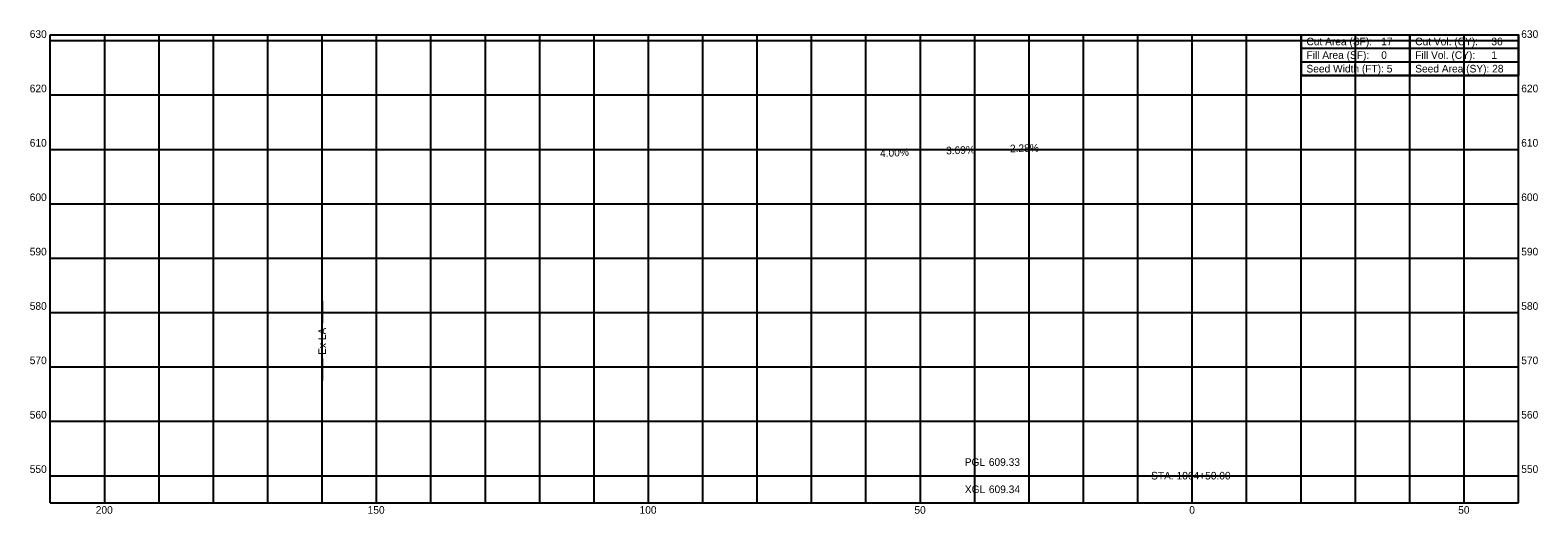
# Model space of a CAD drawing. Extents: x -214 to 64, y 543 to 632.
import ezdxf

# ---------------------------------------------------------------- set-up
doc = ezdxf.new("R2010")
doc.units = 0
for name, color, linetype in [('Default', 7, 'Continuous'), ('DT_X_Void', 7, 'Continuous'), ('SH_Data', 7, 'Continuous'), ('SH_Major_Grid_Line', 7, 'Continuous'), ('SH_Masking', 7, 'Continuous'), ('SH_Text', 7, 'Continuous')]:
    doc.layers.add(name, color=color, linetype=linetype)

msp = doc.modelspace()

# ---------------------------------------------------------------- linework, layer by layer
at = {"layer": 'Default'}
msp.add_circle((60, 631.09), 0.000833, dxfattribs=at)
msp.add_circle((60, 631.09), 0.000833, dxfattribs=at)
msp.add_circle((60, 631.09), 0.000833, dxfattribs=at)
msp.add_circle((60, 631.09), 0.000833, dxfattribs=at)
msp.add_circle((60, 631.09), 0.000833, dxfattribs=at)
msp.add_circle((60, 631.09), 0.000833, dxfattribs=at)
msp.add_circle((60, 631.09), 0.000833, dxfattribs=at)
msp.add_circle((60, 631.09), 0.000833, dxfattribs=at)
msp.add_circle((60, 631.09), 0.000833, dxfattribs=at)
msp.add_circle((60, 631.09), 0.000833, dxfattribs=at)
msp.add_circle((60, 631.09), 0.000833, dxfattribs=at)
msp.add_circle((60, 631.09), 0.000833, dxfattribs=at)
at = {"layer": 'DT_X_Void'}
for p, q in [((-160, 582.14), (-160, 578.07)), ((-160, 571.56), (-160, 567.49))]:
    msp.add_line(p, q, dxfattribs=at)
at = {"layer": 'SH_Data'}
for p, q in [((20, 631.09), (60, 631.09)), ((20, 631.09), (20, 626.09)), ((40, 631.09), (40, 623.59)), ((60, 631.09), (60, 626.09)), ((20, 628.59), (60, 628.59)), ((20, 626.09), (60, 626.09)), ((36.6, 624.84), (36.6, 624.84)), ((55.89, 624.84), (55.89, 624.84))]:
    msp.add_line(p, q, dxfattribs=at)
msp.add_lwpolyline([(20, 626.09), (20, 623.59), (60, 623.59), (60, 626.09)], dxfattribs=at)
at = {"layer": 'SH_Major_Grid_Line'}
for p, q in [((-210, 631.09), (60, 631.09)), ((-210, 545), (-210, 631.09)), ((-210, 630), (60, 630)), ((-200, 545), (-200, 631.09)), ((-190, 545), (-190, 631.09)), ((-180, 545), (-180, 631.09)), ((-170, 545), (-170, 631.09)), ((-160, 545), (-160, 631.09)), ((-150, 545), (-150, 631.09)), ((-140, 545), (-140, 631.09)), ((-130, 545), (-130, 631.09)), ((-120, 545), (-120, 631.09)), ((-110, 545), (-110, 631.09)), ((-100, 545), (-100, 631.09)), ((-90, 545), (-90, 631.09)), ((-80, 545), (-80, 631.09)), ((-70, 545), (-70, 631.09)), ((-60, 545), (-60, 631.09)), ((-50, 545), (-50, 631.09)), ((-40, 545), (-40, 631.09)), ((-30, 545), (-30, 631.09)), ((-20, 545), (-20, 631.09)), ((-10, 545), (-10, 631.09)), ((0, 545), (0, 631.09)), ((10, 545), (10, 631.09)), ((20, 545), (20, 631.09)), ((30, 545), (30, 631.09)), ((40, 545), (40, 631.09)), ((50, 545), (50, 631.09)), ((60, 545), (60, 631.09)), ((-210, 620), (60, 620)), ((-210, 610), (60, 610)), ((-210, 600), (60, 600)), ((-210, 590), (60, 590)), ((-210, 580), (60, 580)), ((-210, 570), (60, 570)), ((-210, 560), (60, 560)), ((-210, 550), (60, 550)), ((-210, 545), (60, 545))]:
    msp.add_line(p, q, dxfattribs=at)
at = {"layer": 'SH_Masking'}
msp.add_lwpolyline([(20, 631.09), (60, 631.09), (60, 623.59), (20, 623.59)], close=True, dxfattribs=at)

# ---------------------------------------------------------------- texts
at = {"layer": 'DT_X_Void'}
msp.add_text('Ex LA', height=1.4, rotation=90, dxfattribs=at).set_placement((-159.3, 572.2))
at = {"layer": 'SH_Text'}
for s, p in [('630', (-213.78, 630.5)), ('Cut Area (SF):', (21, 629.14)), ('17', (34.75, 629.14)), ('Cut Vol. (CY):', (41, 629.14)), ('36', (55, 629.14)), ('630', (60.5, 630.5)), ('Fill Area (SF):', (21, 626.64)), ('0', (34.75, 626.64)), ('Fill Vol. (CY):', (41, 626.64)), ('1', (55, 626.64)), ('Seed Width (FT): 5', (21, 624.14)), ('Seed Area (SY): 28', (41, 624.14)), ('620', (-213.78, 620.5)), ('620', (60.5, 620.5)), ('610', (-213.78, 610.5)), ('610', (60.5, 610.5)), ('600', (-213.78, 600.5)), ('600', (60.5, 600.5)), ('590', (-213.78, 590.5)), ('590', (60.5, 590.5)), ('580', (-213.78, 580.5)), ('580', (60.5, 580.5)), ('570', (-213.78, 570.5)), ('570', (60.5, 570.5)), ('560', (-213.78, 560.5)), ('560', (60.5, 560.5)), ('550', (-213.78, 550.5)), ('PGL ', (-41.84, 551.8)), ('609.33', (-37.41, 551.8)), ('550', (60.5, 550.5)), ('STA. 1064+50.00', (-7.57, 549.3)), ('XGL ', (-41.82, 546.8)), ('609.34', (-37.4, 546.8)), ('200', (-201.64, 543)), ('150', (-151.64, 543)), ('100', (-101.64, 543)), ('50', (-51.1, 543)), ('0', (-0.55, 543)), ('50', (48.9, 543))]:
    msp.add_text(s, height=1.4, dxfattribs=at).set_placement(p)
for s, rotation, p in [('4.00%', 2.291, (-57.39, 608.59)), ('3.69%', 2.115, (-45.25, 609.07)), ('2.28%', 1.3075, (-33.51, 609.46))]:
    msp.add_text(s, height=1.4, rotation=rotation, dxfattribs=at).set_placement(p)

doc.saveas('drawing.dxf')
